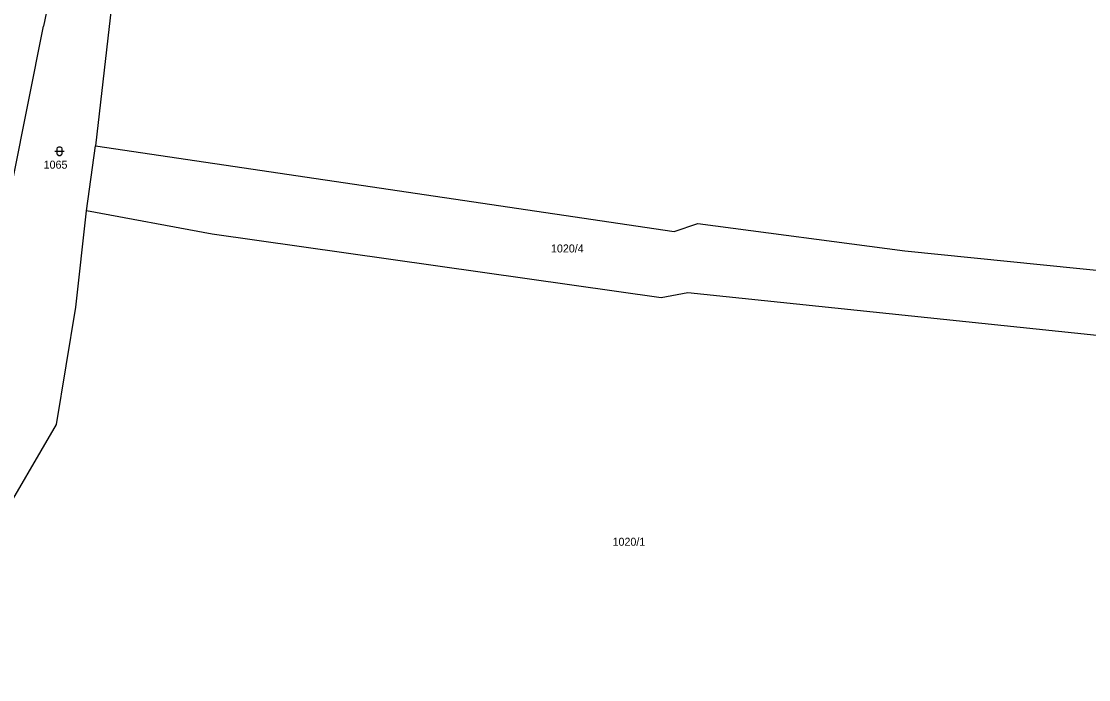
# Model space of a CAD drawing. Extents: x -852001 to -842497, y -1063614 to -1052182.
# Drawn here: x -849632.7 to -849406, y -1056861.7 to -1056721.8 of the extents above; entities that cross this region are included whole.
import ezdxf

# ---------------------------------------------------------------- set-up
doc = ezdxf.new("R2010")
doc.units = 0
for name, color, linetype in [('Default', 7, 'Continuous'), ('KN_HRANICE', 7, 'Continuous'), ('KN_KULTURY', 7, 'Continuous'), ('KN_PARCELY', 7, 'Continuous')]:
    doc.layers.add(name, color=color, linetype=linetype)

# ---------------------------------------------------------------- blocks, each defined once
blk = doc.blocks.new('316')
at = {"layer": 'Default'}
for points in [[(-1, 1), (0.27, 1), (1, 1)], [(-0.5, 1.5), (-0.4, 1.79), (-0.15, 1.97), (0.16, 1.97), (0.41, 1.79), (0.51, 1.5), (0.51, 0.5), (0.41, 0.21), (0.16, 0.03), (-0.15, 0.03), (-0.4, 0.21), (-0.5, 0.5), (-0.5, 1.5)]]:
    blk.add_lwpolyline(points, dxfattribs=at)

msp = doc.modelspace()

# ---------------------------------------------------------------- linework, layer by layer
at = {"layer": 'KN_HRANICE'}
for p, q in [((-849609.39, -1056634.86), (-849628.03, -1056722.82)), ((-849609.39, -1056634.86), (-849628.03, -1056722.82)), ((-849613.57, -1056718.57), (-849616.94, -1056748.2)), ((-849613.57, -1056718.57), (-849616.94, -1056748.2)), ((-849652.87, -1056847.29), (-849628.03, -1056722.82)), ((-849652.87, -1056847.29), (-849628.03, -1056722.82)), ((-849618.87, -1056762.03), (-849616.94, -1056748.2)), ((-849618.87, -1056762.03), (-849616.94, -1056748.2)), ((-849616.94, -1056748.2), (-849494.02, -1056766.41)), ((-849616.94, -1056748.2), (-849494.02, -1056766.41)), ((-849621.16, -1056782.48), (-849618.87, -1056762.03)), ((-849621.16, -1056782.48), (-849618.87, -1056762.03)), ((-849592.21, -1056766.96), (-849618.87, -1056762.03)), ((-849592.21, -1056766.96), (-849618.87, -1056762.03)), ((-849494.02, -1056766.41), (-849489.01, -1056764.72)), ((-849494.02, -1056766.41), (-849489.01, -1056764.72)), ((-849489.01, -1056764.72), (-849445.01, -1056770.52)), ((-849489.01, -1056764.72), (-849445.01, -1056770.52)), ((-849496.77, -1056780.54), (-849592.21, -1056766.96)), ((-849496.77, -1056780.54), (-849592.21, -1056766.96)), ((-849445.01, -1056770.52), (-849389.98, -1056776.11)), ((-849445.01, -1056770.52), (-849389.98, -1056776.11)), ((-849491.12, -1056779.44), (-849496.77, -1056780.54)), ((-849491.12, -1056779.44), (-849496.77, -1056780.54)), ((-849390.25, -1056790.03), (-849491.12, -1056779.44)), ((-849390.25, -1056790.03), (-849491.12, -1056779.44)), ((-849625.23, -1056807.43), (-849621.16, -1056782.48)), ((-849625.23, -1056807.43), (-849621.16, -1056782.48)), ((-849656.96, -1056861.67), (-849625.23, -1056807.43)), ((-849656.96, -1056861.67), (-849625.23, -1056807.43))]:
    msp.add_line(p, q, dxfattribs=at)

# ---------------------------------------------------------------- block references
at = {"layer": 'KN_KULTURY'}
msp.add_blockref('316', (-849624.62, -1056750.37), dxfattribs=at)
msp.add_blockref('316', (-849624.62, -1056750.37), dxfattribs=at)

# ---------------------------------------------------------------- texts
at = {"layer": 'KN_PARCELY'}
for s, p in [('1065', (-849627.98, -1056753.07)), ('1065', (-849627.98, -1056753.07)), ('1020/4', (-849520.21, -1056770.88)), ('1020/4', (-849520.21, -1056770.88)), ('1020/1', (-849507.13, -1056833.21)), ('1020/1', (-849507.13, -1056833.21))]:
    msp.add_text(s, height=1.7, dxfattribs=at).set_placement(p)

doc.saveas('drawing.dxf')
